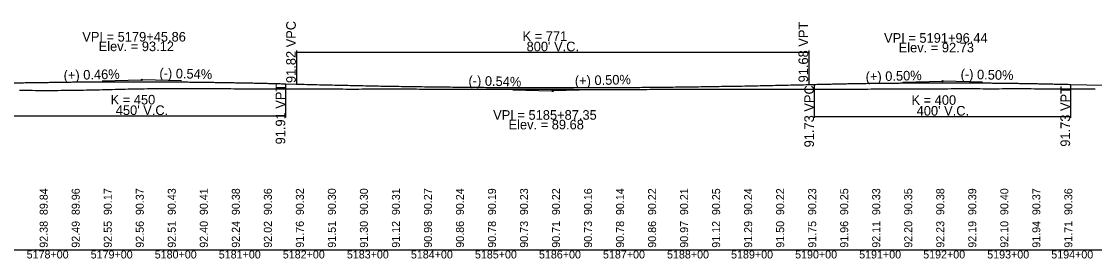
# Model space of a CAD drawing. Extents: x 2121671 to 2169879, y 557274 to 599957.
# Drawn here: x 2147326 to 2149002, y 582173 to 582544 of the extents above; entities that cross this region are included whole.
import ezdxf

# ---------------------------------------------------------------- set-up
doc = ezdxf.new("R2010")
doc.units = 0
for name, color, linetype in [('RD_DDB_GradeTX', 7, 'Continuous'), ('RD_DDB_Profile_EX', 7, 'Continuous'), ('RD_DDB_Profile_Lbl', 7, 'Continuous'), ('RD_DDB_Profile_PR', 7, 'Continuous'), ('RD_DDB_StaTX', 7, 'Continuous'), ('RD_DDB_StripGrade', 7, 'Continuous'), ('RD_DDB_VCLbl', 7, 'Continuous'), ('RD_GPK_Profile_Cell', 7, 'Continuous')]:
    doc.layers.add(name, color=color, linetype=linetype)

msp = doc.modelspace()

# ---------------------------------------------------------------- linework, layer by layer
at = {"layer": 'RD_DDB_GradeTX'}
for p, q in [((2147451.8, 582451), (2147512.8, 582452.4)), ((2147575.8, 582450.8), (2147514.8, 582452.4)), ((2148702.4, 582448.9), (2148763.4, 582450.5)), ((2148826.4, 582448.9), (2148765.4, 582450.5)), ((2148093.3, 582436.9), (2148154.3, 582435.2)), ((2148217.3, 582436.8), (2148156.3, 582435.2))]:
    msp.add_line(p, q, dxfattribs=at)
for centre in [(2147513.8, 582452.4), (2148764.4, 582450.5), (2148155.3, 582435.2)]:
    msp.add_circle(centre, 1, dxfattribs=at)
at = {"layer": 'RD_DDB_Profile_EX'}
for points in [[(2147322.7, 582436.3), (2147327.7, 582436.3), (2147332.7, 582436.3), (2147337.7, 582436.2), (2147342.7, 582436.2), (2147347.7, 582436.1), (2147352.7, 582436.1), (2147357.7, 582436.1), (2147362.7, 582436), (2147367.7, 582436), (2147372.7, 582436), (2147377.7, 582436.1), (2147382.7, 582436.1), (2147387.7, 582436.2), (2147392.7, 582436.3), (2147397.7, 582436.3), (2147402.7, 582436.4), (2147407.7, 582436.4), (2147412.7, 582436.5), (2147417.7, 582436.6), (2147422.7, 582436.7), (2147427.7, 582436.8), (2147432.7, 582436.9), (2147437.7, 582437), (2147442.7, 582437.1), (2147447.7, 582437.2), (2147452.7, 582437.3), (2147457.7, 582437.4), (2147462.7, 582437.6), (2147467.7, 582437.7), (2147472.7, 582437.8), (2147477.7, 582437.9), (2147482.7, 582438.1), (2147487.7, 582438.2), (2147492.7, 582438.3), (2147497.7, 582438.4), (2147502.7, 582438.4), (2147507.7, 582438.5), (2147512.7, 582438.6), (2147517.7, 582438.7), (2147522.7, 582438.8), (2147527.7, 582438.8), (2147532.7, 582438.9), (2147537.7, 582438.9), (2147542.7, 582438.9), (2147547.7, 582438.9), (2147552.7, 582438.9), (2147557.7, 582438.9), (2147562.7, 582439), (2147567.7, 582439), (2147572.7, 582439), (2147577.7, 582439), (2147582.7, 582438.9), (2147587.7, 582438.9), (2147592.7, 582438.9), (2147597.7, 582438.9), (2147602.7, 582438.9), (2147607.7, 582438.9), (2147612.7, 582438.9), (2147617.7, 582438.9), (2147622.7, 582438.8), (2147627.7, 582438.8), (2147632.7, 582438.8), (2147637.7, 582438.8), (2147642.7, 582438.8), (2147647.7, 582438.8), (2147652.7, 582438.8), (2147657.7, 582438.7), (2147662.7, 582438.7), (2147667.7, 582438.7), (2147672.7, 582438.7), (2147677.7, 582438.7), (2147682.7, 582438.7), (2147687.7, 582438.7), (2147692.7, 582438.7), (2147697.7, 582438.7), (2147702.7, 582438.6), (2147707.7, 582438.6), (2147712.7, 582438.6), (2147717.7, 582438.6), (2147722.7, 582438.6), (2147727.7, 582438.6)], [(2147727.7, 582438.6), (2147732.7, 582438.6), (2147737.7, 582438.5), (2147742.7, 582438.5), (2147747.7, 582438.5), (2147752.7, 582438.5), (2147757.7, 582438.5), (2147762.7, 582438.4), (2147767.7, 582438.4), (2147772.7, 582438.4), (2147777.7, 582438.4), (2147782.7, 582438.4), (2147787.7, 582438.4), (2147792.7, 582438.4), (2147797.7, 582438.4), (2147802.7, 582438.4), (2147807.7, 582438.4), (2147812.7, 582438.3), (2147817.7, 582438.3), (2147822.7, 582438.3), (2147827.7, 582438.3), (2147832.7, 582438.2), (2147837.7, 582438.2), (2147842.7, 582438.2), (2147847.7, 582438.2), (2147852.7, 582438.2), (2147857.7, 582438.3), (2147862.7, 582438.3), (2147867.7, 582438.3), (2147872.7, 582438.4), (2147877.7, 582438.4), (2147882.7, 582438.4), (2147887.7, 582438.4), (2147892.7, 582438.4), (2147897.7, 582438.4), (2147902.7, 582438.4), (2147907.7, 582438.4), (2147912.7, 582438.4), (2147917.7, 582438.4), (2147922.7, 582438.4), (2147927.7, 582438.3), (2147932.7, 582438.3), (2147937.7, 582438.3), (2147942.7, 582438.3), (2147947.7, 582438.2), (2147952.7, 582438.2), (2147957.7, 582438.2), (2147962.7, 582438.2), (2147967.7, 582438.2), (2147972.7, 582438.2), (2147977.7, 582438.2), (2147982.7, 582438.2), (2147987.7, 582438.2), (2147992.7, 582438.2), (2147997.7, 582438.2), (2148002.7, 582438.2), (2148007.7, 582438.2), (2148012.7, 582438.1), (2148017.7, 582438.1), (2148022.7, 582438), (2148027.7, 582437.9), (2148032.7, 582437.9), (2148037.7, 582437.8), (2148042.7, 582437.8), (2148047.7, 582437.8), (2148052.7, 582437.8), (2148057.7, 582437.8), (2148062.7, 582437.8), (2148067.7, 582437.8), (2148072.7, 582437.8), (2148077.7, 582437.8), (2148082.7, 582437.8), (2148087.7, 582437.8), (2148092.7, 582437.9), (2148097.7, 582437.9), (2148102.7, 582437.9), (2148107.7, 582437.9), (2148112.7, 582437.9), (2148117.7, 582438), (2148122.7, 582438), (2148127.7, 582438), (2148132.7, 582438), (2148137.7, 582438), (2148142.7, 582438), (2148147.7, 582438), (2148152.7, 582438), (2148157.7, 582438), (2148162.7, 582438), (2148167.7, 582437.9), (2148172.7, 582437.9), (2148177.7, 582437.9), (2148182.7, 582437.8), (2148187.7, 582437.8), (2148192.7, 582437.7), (2148197.7, 582437.7), (2148202.7, 582437.6), (2148207.7, 582437.6), (2148212.7, 582437.6), (2148217.7, 582437.6), (2148222.7, 582437.6), (2148227.7, 582437.6)], [(2148227.7, 582437.6), (2148232.7, 582437.6), (2148237.7, 582437.6), (2148242.7, 582437.6), (2148247.7, 582437.6), (2148252.7, 582437.6), (2148257.7, 582437.5), (2148262.7, 582437.5), (2148267.7, 582437.5), (2148272.7, 582437.5), (2148277.7, 582437.5), (2148282.7, 582437.5), (2148287.7, 582437.5), (2148292.7, 582437.6), (2148297.7, 582437.6), (2148302.7, 582437.7), (2148307.7, 582437.8), (2148312.7, 582437.8), (2148317.7, 582437.9), (2148322.7, 582438), (2148327.7, 582438), (2148332.7, 582438), (2148337.7, 582437.9), (2148342.7, 582437.9), (2148347.7, 582437.9), (2148352.7, 582437.9), (2148357.7, 582437.9), (2148362.7, 582437.8), (2148367.7, 582437.9), (2148372.7, 582437.9), (2148377.7, 582438), (2148382.7, 582438), (2148387.7, 582438.1), (2148392.7, 582438.1), (2148397.7, 582438.1), (2148402.7, 582438.2), (2148407.7, 582438.1), (2148412.7, 582438.1), (2148417.7, 582438.1), (2148422.7, 582438.1), (2148427.7, 582438), (2148432.7, 582438), (2148437.7, 582438), (2148442.7, 582437.9), (2148447.7, 582438), (2148452.7, 582438), (2148457.7, 582438), (2148462.7, 582438), (2148467.7, 582438), (2148472.7, 582438), (2148477.7, 582438.1), (2148482.7, 582438.1), (2148487.7, 582438), (2148492.7, 582438), (2148497.7, 582438), (2148502.7, 582438), (2148507.7, 582438), (2148512.7, 582437.9), (2148517.7, 582437.9), (2148522.7, 582437.9), (2148527.7, 582437.9), (2148532.7, 582437.9), (2148537.7, 582437.9), (2148542.7, 582437.9), (2148547.7, 582437.9), (2148552.7, 582437.9), (2148557.7, 582437.9), (2148562.7, 582437.9), (2148567.7, 582438), (2148572.7, 582438), (2148577.7, 582438), (2148582.7, 582438), (2148587.7, 582438), (2148592.7, 582438), (2148597.7, 582438), (2148602.7, 582438.1), (2148607.7, 582438.1), (2148612.7, 582438.1), (2148617.7, 582438.1), (2148622.7, 582438.1), (2148627.7, 582438.1), (2148632.7, 582438.1), (2148637.7, 582438.1), (2148642.7, 582438.1), (2148647.7, 582438.2), (2148652.7, 582438.3), (2148657.7, 582438.4), (2148662.7, 582438.4), (2148667.7, 582438.5), (2148672.7, 582438.6), (2148677.7, 582438.6), (2148682.7, 582438.7), (2148687.7, 582438.7), (2148692.7, 582438.7), (2148697.7, 582438.6), (2148702.7, 582438.6), (2148707.7, 582438.6), (2148712.7, 582438.6), (2148717.7, 582438.6), (2148722.7, 582438.6), (2148727.7, 582438.6)], [(2148727.7, 582438.6), (2148732.7, 582438.6), (2148737.7, 582438.6), (2148742.7, 582438.7), (2148747.7, 582438.7), (2148752.7, 582438.7), (2148757.7, 582438.7), (2148762.7, 582438.7), (2148767.7, 582438.7), (2148772.7, 582438.7), (2148777.7, 582438.8), (2148782.7, 582438.8), (2148787.7, 582438.8), (2148792.7, 582438.8), (2148797.7, 582438.8), (2148802.7, 582438.8), (2148807.7, 582438.8), (2148812.7, 582438.8), (2148817.7, 582438.8), (2148822.7, 582438.8), (2148827.7, 582438.7), (2148832.7, 582438.7), (2148837.7, 582438.7), (2148842.7, 582438.7), (2148847.7, 582438.7), (2148852.7, 582438.7), (2148857.7, 582438.8), (2148862.7, 582438.8), (2148867.7, 582438.8), (2148872.7, 582438.9), (2148877.7, 582438.9), (2148882.7, 582438.9), (2148887.7, 582438.8), (2148892.7, 582438.8), (2148897.7, 582438.8), (2148902.7, 582438.8), (2148907.7, 582438.7), (2148912.7, 582438.7), (2148917.7, 582438.7), (2148922.7, 582438.7), (2148927.7, 582438.6), (2148932.7, 582438.6), (2148937.7, 582438.6), (2148942.7, 582438.6), (2148947.7, 582438.6), (2148952.7, 582438.6), (2148957.7, 582438.6), (2148962.7, 582438.6), (2148967.7, 582438.6), (2148972.7, 582438.6), (2148977.7, 582438.6), (2148982.7, 582438.6), (2148987.7, 582438.6), (2148992.7, 582438.6), (2148997.7, 582438.6), (2149002.7, 582438.5)]]:
    msp.add_lwpolyline(points, dxfattribs=at)
at = {"layer": 'RD_DDB_Profile_PR'}
for p, q in [((2147738.8, 582446.4), (2147755.3, 582445.9)), ((2148555.3, 582445.2), (2148564.4, 582445.5)), ((2148964.4, 582445.5), (2149161.2, 582440.6))]:
    msp.add_line(p, q, dxfattribs=at)
for points in [[(2147288.8, 582447.2), (2147297.8, 582447.4), (2147306.8, 582447.6), (2147315.8, 582447.8), (2147324.8, 582448), (2147333.8, 582448.2), (2147342.8, 582448.3), (2147351.8, 582448.5), (2147360.8, 582448.6), (2147369.8, 582448.7), (2147378.8, 582448.9), (2147387.8, 582449), (2147396.8, 582449.1), (2147405.8, 582449.2), (2147414.8, 582449.3), (2147423.8, 582449.3), (2147432.8, 582449.4), (2147441.8, 582449.5), (2147450.8, 582449.5), (2147459.8, 582449.6), (2147468.8, 582449.6), (2147477.8, 582449.6), (2147486.8, 582449.6), (2147495.8, 582449.6), (2147504.8, 582449.6), (2147513.8, 582449.6), (2147522.8, 582449.6), (2147531.8, 582449.6), (2147540.8, 582449.5), (2147549.8, 582449.5), (2147558.8, 582449.4), (2147567.8, 582449.4), (2147576.8, 582449.3), (2147585.8, 582449.2), (2147594.8, 582449.1), (2147603.8, 582449), (2147612.8, 582448.9), (2147621.8, 582448.8), (2147630.8, 582448.6), (2147639.8, 582448.5), (2147648.8, 582448.4), (2147657.8, 582448.2), (2147666.8, 582448), (2147675.8, 582447.9), (2147684.8, 582447.7), (2147693.8, 582447.5), (2147702.8, 582447.3), (2147711.8, 582447.1), (2147720.8, 582446.9), (2147729.8, 582446.6), (2147738.8, 582446.4)], [(2147755.3, 582445.9), (2147771.3, 582445.5), (2147787.3, 582445.1), (2147803.3, 582444.7), (2147819.3, 582444.4), (2147835.3, 582444), (2147851.3, 582443.7), (2147867.3, 582443.3), (2147883.3, 582443), (2147899.3, 582442.8), (2147915.3, 582442.5), (2147931.3, 582442.2), (2147947.3, 582442), (2147963.3, 582441.8), (2147979.3, 582441.6), (2147995.3, 582441.4), (2148011.3, 582441.2), (2148027.3, 582441), (2148043.3, 582440.9), (2148059.3, 582440.8), (2148075.3, 582440.7), (2148091.3, 582440.6), (2148107.3, 582440.5), (2148123.3, 582440.5), (2148139.3, 582440.4), (2148155.3, 582440.4), (2148171.3, 582440.4), (2148187.3, 582440.4), (2148203.3, 582440.4), (2148219.3, 582440.5), (2148235.3, 582440.5), (2148251.3, 582440.6), (2148267.3, 582440.7), (2148283.3, 582440.8), (2148299.3, 582440.9), (2148315.3, 582441.1), (2148331.3, 582441.3), (2148347.3, 582441.4), (2148363.3, 582441.6), (2148379.3, 582441.8), (2148395.3, 582442.1), (2148411.3, 582442.3), (2148427.3, 582442.6), (2148443.3, 582442.8), (2148459.3, 582443.1), (2148475.3, 582443.4), (2148491.3, 582443.8), (2148507.3, 582444.1), (2148523.3, 582444.5), (2148539.3, 582444.8), (2148555.3, 582445.2)], [(2148564.4, 582445.5), (2148572.4, 582445.7), (2148580.4, 582445.9), (2148588.4, 582446), (2148596.4, 582446.2), (2148604.4, 582446.4), (2148612.4, 582446.5), (2148620.4, 582446.7), (2148628.4, 582446.8), (2148636.4, 582446.9), (2148644.4, 582447.1), (2148652.4, 582447.2), (2148660.4, 582447.3), (2148668.4, 582447.4), (2148676.4, 582447.5), (2148684.4, 582447.6), (2148692.4, 582447.6), (2148700.4, 582447.7), (2148708.4, 582447.8), (2148716.4, 582447.8), (2148724.4, 582447.9), (2148732.4, 582447.9), (2148740.4, 582447.9), (2148748.4, 582448), (2148756.4, 582448), (2148764.4, 582448), (2148772.4, 582448), (2148780.4, 582448), (2148788.4, 582447.9), (2148796.4, 582447.9), (2148804.4, 582447.9), (2148812.4, 582447.8), (2148820.4, 582447.8), (2148828.4, 582447.7), (2148836.4, 582447.7), (2148844.4, 582447.6), (2148852.4, 582447.5), (2148860.4, 582447.4), (2148868.4, 582447.3), (2148876.4, 582447.2), (2148884.4, 582447.1), (2148892.4, 582447), (2148900.4, 582446.8), (2148908.4, 582446.7), (2148916.4, 582446.5), (2148924.4, 582446.4), (2148932.4, 582446.2), (2148940.4, 582446), (2148948.4, 582445.9), (2148956.4, 582445.7), (2148964.4, 582445.5)]]:
    msp.add_spline(points, degree=3, dxfattribs=at)
at = {"layer": 'RD_DDB_VCLbl'}
for p, q in [((2147755.3, 582498.4), (2147755.3, 582445.9)), ((2147755.3, 582495.9), (2148555.3, 582495.9)), ((2148555.3, 582498.4), (2148555.3, 582445.2)), ((2147738.8, 582393.9), (2147738.8, 582446.4)), ((2148564.4, 582393), (2148564.4, 582445.5)), ((2148964.4, 582393), (2148964.4, 582445.5)), ((2147288.8, 582396.4), (2147738.8, 582396.4)), ((2148564.4, 582395.5), (2148964.4, 582395.5))]:
    msp.add_line(p, q, dxfattribs=at)
at = {"layer": 'RD_GPK_Profile_Cell'}
msp.add_line((2146667.9, 582186.8), (2151167.9, 582186.8), dxfattribs=at)

# ---------------------------------------------------------------- texts
at = {"layer": 'RD_DDB_GradeTX'}
for s, rotation, p in [('(+) 0.46%', 1.3258, (2147391.9, 582452.2)), ('(-) 0.54%', 358.4628, (2147541.1, 582455.8)), ('(+) 0.50%', 1.4356, (2148644.3, 582450)), ('(-) 0.50%', 358.5698, (2148792.3, 582454.2)), ('(-) 0.54%', 358.4628, (2148023.8, 582444.1)), ('(+) 0.50%', 1.4356, (2148190.2, 582443.6))]:
    msp.add_text(s, height=15, rotation=rotation, dxfattribs=at).set_placement(p)
at = {"layer": 'RD_DDB_Profile_Lbl'}
for s, p in [('VPI = 5179+45.86', (2147420.9, 582512.4)), ('VPI = 5191+96.44', (2148672.9, 582510.5)), ('Elev. = 93.12', (2147446.4, 582497.4)), ('Elev. = 92.73', (2148695.7, 582495.5)), ('VPI = 5185+87.35', (2148062.5, 582390.2)), ('Elev. = 89.68', (2148086.5, 582375.2))]:
    msp.add_text(s, height=15, dxfattribs=at).set_placement(p)
at = {"layer": 'RD_DDB_StaTX'}
for s, p in [('5178+00', (2147334, 582173.5)), ('5179+00', (2147434, 582173.5)), ('5180+00', (2147534, 582173.5)), ('5181+00', (2147634, 582173.5)), ('5182+00', (2147734, 582173.5)), ('5183+00', (2147834, 582173.5)), ('5184+00', (2147934, 582173.5)), ('5185+00', (2148034, 582173.5)), ('5186+00', (2148134, 582173.5)), ('5187+00', (2148234, 582173.5)), ('5188+00', (2148334, 582173.5)), ('5189+00', (2148434, 582173.5)), ('5190+00', (2148534, 582173.5)), ('5191+00', (2148634, 582173.5)), ('5192+00', (2148734, 582173.5)), ('5193+00', (2148834, 582173.5)), ('5194+00', (2148934, 582173.5))]:
    msp.add_text(s, height=12.5, dxfattribs=at).set_placement(p)
at = {"layer": 'RD_DDB_StripGrade'}
for s, height, p in [('91.82 VPC', 15, (2147754.3, 582447.6)), ('91.68 VPT', 15, (2148554.3, 582448.6)), ('91.91 VPT', 15, (2147737.8, 582351.7)), ('91.73 VPC', 15, (2148563.4, 582347.1)), ('91.73 VPT', 15, (2148963.4, 582348.1)), ('89.84', 12.5, (2147366.9, 582241.3)), ('89.96', 12.5, (2147416.9, 582241.3)), ('90.17', 12.5, (2147466.9, 582241.3)), ('90.37', 12.5, (2147516.9, 582241.3)), ('90.43', 12.5, (2147566.9, 582241.3)), ('90.41', 12.5, (2147616.9, 582241.3)), ('90.38', 12.5, (2147666.9, 582241.3)), ('90.36', 12.5, (2147716.9, 582241.3)), ('90.32', 12.5, (2147766.9, 582241.3)), ('90.30', 12.5, (2147816.9, 582241.3)), ('90.30', 12.5, (2147866.9, 582241.3)), ('90.31', 12.5, (2147916.9, 582241.3)), ('90.27', 12.5, (2147966.9, 582241.3)), ('90.24', 12.5, (2148016.9, 582241.3)), ('90.19', 12.5, (2148066.9, 582241.3)), ('90.23', 12.5, (2148116.9, 582241.3)), ('90.22', 12.5, (2148166.9, 582241.3)), ('90.16', 12.5, (2148216.9, 582241.3)), ('90.14', 12.5, (2148266.9, 582241.3)), ('90.22', 12.5, (2148316.9, 582241.3)), ('90.21', 12.5, (2148366.9, 582241.3)), ('90.25', 12.5, (2148416.9, 582241.3)), ('90.24', 12.5, (2148466.9, 582241.3)), ('90.22', 12.5, (2148516.9, 582241.3)), ('90.23', 12.5, (2148566.9, 582241.3)), ('90.25', 12.5, (2148616.9, 582241.3)), ('90.33', 12.5, (2148666.9, 582241.3)), ('90.35', 12.5, (2148716.9, 582241.3)), ('90.38', 12.5, (2148766.9, 582241.3)), ('90.39', 12.5, (2148816.9, 582241.3)), ('90.40', 12.5, (2148866.9, 582241.3)), ('90.37', 12.5, (2148916.9, 582241.3)), ('90.36', 12.5, (2148966.9, 582241.3)), ('92.38', 12.5, (2147366.9, 582190.3)), ('92.49', 12.5, (2147416.9, 582190.3)), ('92.55', 12.5, (2147466.9, 582190.3)), ('92.56', 12.5, (2147516.9, 582190.3)), ('92.51', 12.5, (2147566.9, 582190.3)), ('92.40', 12.5, (2147616.9, 582190.3)), ('92.24', 12.5, (2147666.9, 582190.3)), ('92.02', 12.5, (2147716.9, 582190.3)), ('91.76', 12.5, (2147766.9, 582190.3)), ('91.51', 12.5, (2147816.9, 582190.3)), ('91.30', 12.5, (2147866.9, 582190.3)), ('91.12', 12.5, (2147916.9, 582190.3)), ('90.98', 12.5, (2147966.9, 582190.3)), ('90.86', 12.5, (2148016.9, 582190.3)), ('90.78', 12.5, (2148066.9, 582190.3)), ('90.73', 12.5, (2148116.9, 582190.3)), ('90.71', 12.5, (2148166.9, 582190.3)), ('90.73', 12.5, (2148216.9, 582190.3)), ('90.78', 12.5, (2148266.9, 582190.3)), ('90.86', 12.5, (2148316.9, 582190.3)), ('90.97', 12.5, (2148366.9, 582190.3)), ('91.12', 12.5, (2148416.9, 582190.3)), ('91.29', 12.5, (2148466.9, 582190.3)), ('91.50', 12.5, (2148516.9, 582190.3)), ('91.75', 12.5, (2148566.9, 582190.3)), ('91.96', 12.5, (2148616.9, 582190.3)), ('92.11', 12.5, (2148666.9, 582190.3)), ('92.20', 12.5, (2148716.9, 582190.3)), ('92.23', 12.5, (2148766.9, 582190.3)), ('92.19', 12.5, (2148816.9, 582190.3)), ('92.10', 12.5, (2148866.9, 582190.3)), ('91.94', 12.5, (2148916.9, 582190.3)), ('91.71', 12.5, (2148966.9, 582190.3))]:
    msp.add_text(s, height=height, rotation=90, dxfattribs=at).set_placement(p)
at = {"layer": 'RD_DDB_VCLbl'}
for s, p in [('K = 771', (2148108.4, 582513.3)), ("800' V.C.", (2148114.7, 582497.2)), ('K = 450', (2147465.1, 582414.1)), ('K = 400', (2148715.7, 582413.5)), ("450' V.C.", (2147473.2, 582397.6)), ("400' V.C.", (2148723.8, 582396.7))]:
    msp.add_text(s, height=15, dxfattribs=at).set_placement(p)

doc.saveas('drawing.dxf')
